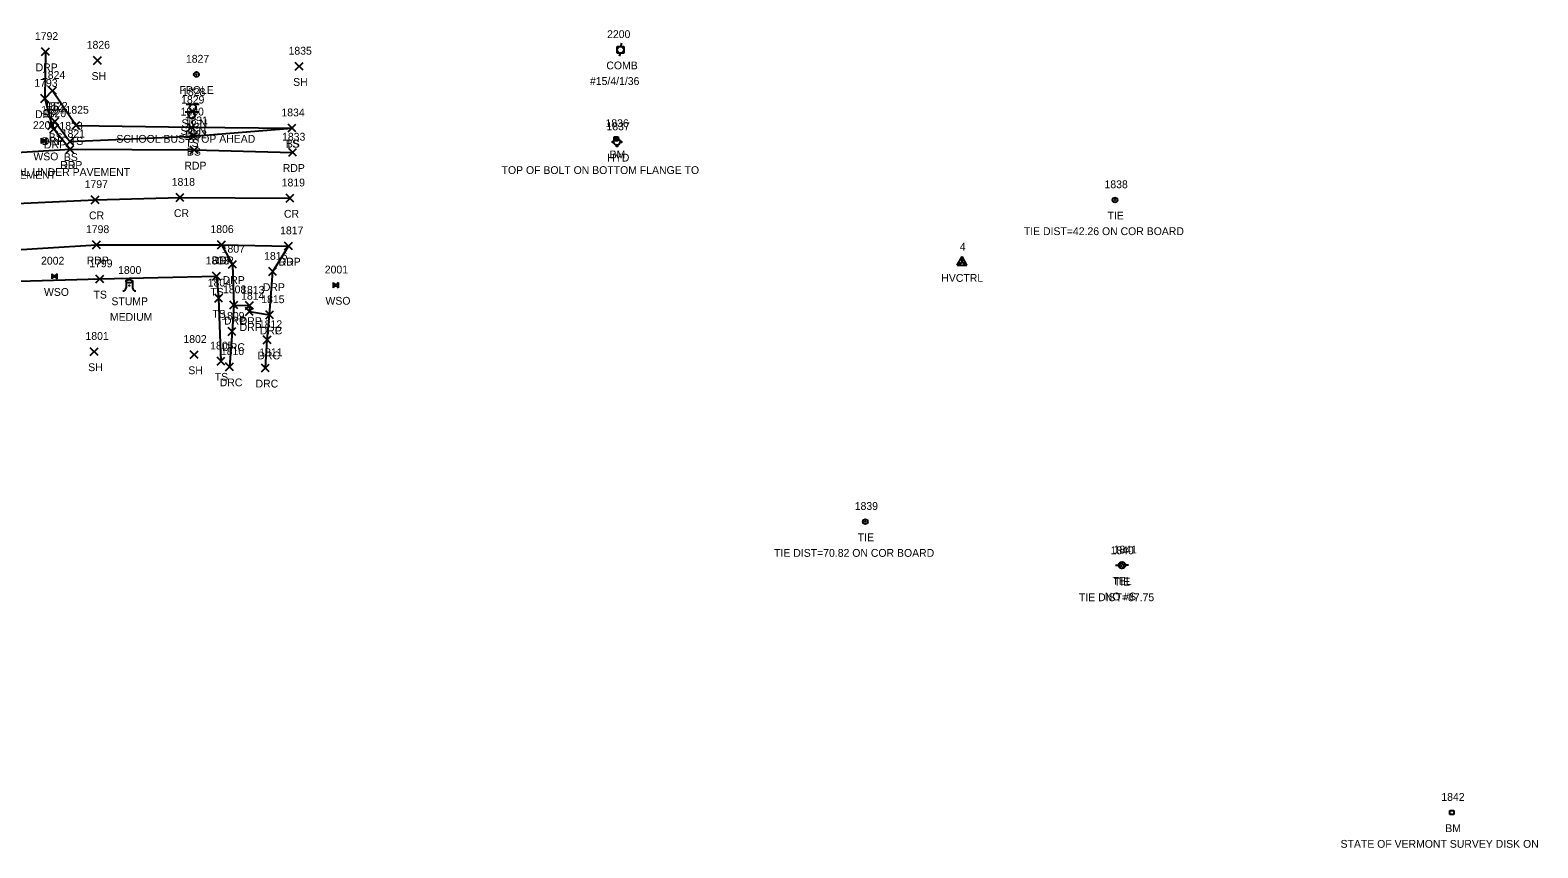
# Model space of a CAD drawing. Extents: x 1761340 to 1763889, y 696770 to 706023.
# Drawn here: x 1761969.7 to 1762355.3, y 700706.9 to 700916.1 of the extents above; entities that cross this region are included whole.
import ezdxf

# ---------------------------------------------------------------- set-up
doc = ezdxf.new("R2010")
doc.units = 0
for name, color, linetype in [('C_A', 7, 'Continuous'), ('C_C', 7, 'Continuous'), ('C_I', 7, 'Continuous'), ('CBP', 7, 'Continuous'), ('CPBM', 7, 'Continuous'), ('CPSM', 7, 'Continuous'), ('L_A', 7, 'Continuous'), ('L_C', 7, 'Continuous'), ('L_I', 7, 'Continuous'), ('L_TIC', 7, 'Continuous'), ('LELB', 7, 'Continuous'), ('LFP', 7, 'Continuous'), ('LTS', 7, 'Continuous'), ('P_A', 7, 'Continuous'), ('P_I', 7, 'Continuous'), ('P_TIC', 7, 'Continuous'), ('PET', 7, 'Continuous'), ('PRC', 7, 'Continuous'), ('R_A', 7, 'Continuous'), ('R_I', 7, 'Continuous'), ('R_TIC', 7, 'Continuous'), ('RDP', 7, 'Continuous'), ('S_A', 7, 'Continuous'), ('S_C', 7, 'Continuous'), ('S_I', 7, 'Continuous'), ('SSGN', 7, 'Continuous'), ('U_A', 7, 'Continuous'), ('U_C', 7, 'Continuous'), ('U_I', 7, 'Continuous'), ('UP', 7, 'Continuous'), ('UWFH', 7, 'Continuous'), ('UWV', 7, 'Continuous')]:
    doc.layers.add(name, color=color, linetype=linetype)

msp = doc.modelspace()

# ---------------------------------------------------------------- linework, layer by layer
at = {"layer": 'CBP'}
for centre, radius in [((1762247.16, 700872.67), 0.625), ((1762247.16, 700872.67), 0.0833), ((1762183.28, 700790.36), 0.625), ((1762183.28, 700790.36), 0.0833), ((1762248.79, 700779.01), 0.625), ((1762248.79, 700779.01), 0.0833)]:
    msp.add_circle(centre, radius, dxfattribs=at)
at = {"layer": 'CPBM'}
for p, q in [((1762119.07, 700887.8), (1762119.07, 700888.8)), ((1762119.07, 700888.8), (1762120.07, 700888.8)), ((1762120.07, 700887.8), (1762119.07, 700887.8)), ((1762119.58, 700888.3), (1762119.58, 700888.3)), ((1762119.58, 700888.3), (1762119.58, 700888.3)), ((1762120.07, 700888.8), (1762120.07, 700887.8)), ((1762332.81, 700715.42), (1762332.81, 700716.42)), ((1762332.81, 700716.42), (1762333.81, 700716.42)), ((1762333.81, 700716.42), (1762333.81, 700715.42)), ((1762333.81, 700715.42), (1762332.81, 700715.42)), ((1762333.31, 700715.92), (1762333.31, 700715.92)), ((1762333.31, 700715.92), (1762333.31, 700715.92))]:
    msp.add_line(p, q, dxfattribs=at)
at = {"layer": 'CPSM'}
for p, q in [((1762206.78, 700855.99), (1762208.03, 700858.16)), ((1762206.78, 700855.99), (1762208.03, 700856.72)), ((1762206.78, 700855.99), (1762209.28, 700855.99)), ((1762209.28, 700855.99), (1762208.03, 700858.16)), ((1762208.03, 700856.72), (1762208.03, 700858.16)), ((1762208.03, 700856.72), (1762208.03, 700856.72)), ((1762208.03, 700856.72), (1762209.28, 700855.99))]:
    msp.add_line(p, q, dxfattribs=at)
at = {"layer": 'L_TIC'}
for points in [[(1761985.89, 700907.36), (1761987.89, 700909.36)], [(1761987.89, 700907.36), (1761985.89, 700909.36)], [(1762037.46, 700905.84), (1762039.46, 700907.84)], [(1762039.46, 700905.84), (1762037.46, 700907.84)], [(1761974.38, 700899.63), (1761976.38, 700901.63)], [(1761976.38, 700899.63), (1761974.38, 700901.63)], [(1761974.98, 700891.72), (1761976.98, 700893.72)], [(1761976.98, 700891.72), (1761974.98, 700893.72)], [(1761980.41, 700890.74), (1761982.41, 700892.74)], [(1761982.41, 700890.74), (1761980.41, 700892.74)], [(1762009.93, 700890.26), (1762011.93, 700892.26)], [(1762011.93, 700890.26), (1762009.93, 700892.26)], [(1762010.32, 700888.01), (1762012.32, 700890.01)], [(1762012.32, 700888.01), (1762010.32, 700890.01)], [(1762035.63, 700890.05), (1762037.63, 700892.05)], [(1762037.63, 700890.05), (1762035.63, 700892.05)], [(1762035.63, 700890.05), (1762037.63, 700892.05)], [(1762037.63, 700890.05), (1762035.63, 700892.05)], [(1761978.85, 700886.63), (1761980.85, 700888.63)], [(1761980.85, 700886.63), (1761978.85, 700888.63)], [(1761986.48, 700851.44), (1761988.48, 700853.44)], [(1761988.48, 700851.44), (1761986.48, 700853.44)], [(1762016.34, 700852.16), (1762018.34, 700854.16)], [(1762018.34, 700852.16), (1762016.34, 700854.16)], [(1762016.87, 700846.52), (1762018.87, 700848.52)], [(1762018.87, 700846.52), (1762016.87, 700848.52)], [(1761985.03, 700832.87), (1761987.03, 700834.87)], [(1761987.03, 700832.87), (1761985.03, 700834.87)], [(1762010.64, 700832.08), (1762012.64, 700834.08)], [(1762012.64, 700832.08), (1762010.64, 700834.08)], [(1762017.48, 700830.41), (1762019.48, 700832.41)], [(1762019.48, 700830.41), (1762017.48, 700832.41)]]:
    msp.add_lwpolyline(points, dxfattribs=at)
at = {"layer": 'LELB'}
for points in [[(1761975.38, 700900.63), (1761981.41, 700891.74), (1762010.93, 700891.26), (1762036.63, 700891.05)], [(1761975.98, 700892.72), (1761979.85, 700887.63), (1762011.32, 700889.01), (1762036.63, 700891.05)], [(1761929.79, 700836.15), (1761931.22, 700849.05), (1761960.82, 700851.7), (1761987.48, 700852.44), (1762017.34, 700853.16), (1762017.87, 700847.52), (1762018.48, 700831.41)]]:
    msp.add_lwpolyline(points, dxfattribs=at)
at = {"layer": 'LFP'}
for radius in [0.625, 0.0833]:
    msp.add_circle((1762012.2, 700904.78), radius, dxfattribs=at)
at = {"layer": 'LTS'}
for p, q in [((1761994.19, 700851.88), (1761994.19, 700850.21)), ((1761995.86, 700851.71), (1761995.86, 700851.88)), ((1761995.86, 700851.88), (1761995.86, 700850.21)), ((1761995.03, 700850.74), (1761995.03, 700850.74)), ((1761995.03, 700850.74), (1761995.03, 700850.74)), ((1761995.03, 700850.71), (1761995.03, 700850.71))]:
    msp.add_line(p, q, dxfattribs=at)
msp.add_circle((1761995.03, 700850.74), 0.0833, dxfattribs=at)
for centre, start, end in [((1761993.36, 700850.21), 270, 360), ((1761996.69, 700850.21), 180, 270)]:
    msp.add_arc(centre, 0.833, start, end, dxfattribs=at)
msp.add_ellipse((1761995.03, 700851.88), major_axis=(-0.833, 0), ratio=0.5, dxfattribs=at)
at = {"layer": 'P_TIC'}
for points in [[(1761978.87, 700884.62), (1761980.87, 700886.62)], [(1761980.87, 700884.62), (1761978.87, 700886.62)], [(1762010.62, 700884.45), (1762012.62, 700886.45)], [(1762012.62, 700884.45), (1762010.62, 700886.45)], [(1762035.8, 700883.84), (1762037.8, 700885.84)], [(1762037.8, 700883.84), (1762035.8, 700885.84)], [(1761985.3, 700871.71), (1761987.3, 700873.71)], [(1761987.3, 700871.71), (1761985.3, 700873.71)], [(1762007.01, 700872.29), (1762009.01, 700874.29)], [(1762009.01, 700872.29), (1762007.01, 700874.29)], [(1762035.15, 700872.12), (1762037.15, 700874.12)], [(1762037.15, 700872.12), (1762035.15, 700874.12)], [(1761985.64, 700860.18), (1761987.64, 700862.18)], [(1761987.64, 700860.18), (1761985.64, 700862.18)], [(1762017.61, 700860.2), (1762019.61, 700862.2)], [(1762019.61, 700860.2), (1762017.61, 700862.2)], [(1762034.74, 700859.87), (1762036.74, 700861.87)], [(1762036.74, 700859.87), (1762034.74, 700861.87)]]:
    msp.add_lwpolyline(points, dxfattribs=at)
at = {"layer": 'PET'}
for points in [[(1761729.33, 700852.74), (1761740.9, 700853.18), (1761754.83, 700854.09), (1761780.55, 700856.28), (1761810.22, 700861.14), (1761821.19, 700866.01), (1761839.22, 700868.83), (1761861.11, 700872.05), (1761884.87, 700875.71), (1761913.75, 700879.27), (1761932.44, 700880.62), (1761962.06, 700884.59), (1761979.87, 700885.62), (1762011.62, 700885.45), (1762036.8, 700884.84)], [(1761729.33, 700852.74), (1761727.43, 700840.67), (1761725.47, 700828.38), (1761741.06, 700828.32), (1761766.65, 700830.86), (1761785.9, 700834.25), (1761810.86, 700839.79), (1761840.51, 700846.05), (1761863.89, 700848.79), (1761886.86, 700850.87), (1761909.09, 700853.95), (1761931.55, 700856.46), (1761961.83, 700859.61), (1761986.64, 700861.18), (1762018.61, 700861.2), (1762035.74, 700860.87)]]:
    msp.add_lwpolyline(points, dxfattribs=at)
at = {"layer": 'PRC'}
msp.add_lwpolyline([(1761727.43, 700840.67), (1761741.7, 700841.02), (1761763.59, 700842.8), (1761782.51, 700845.85), (1761809.01, 700850.75), (1761839.73, 700856.65), (1761862.6, 700860.14), (1761886.29, 700863.33), (1761916.3, 700867.26), (1761941.01, 700869.9), (1761962.56, 700871.62), (1761986.3, 700872.71), (1762008.01, 700873.29), (1762036.15, 700873.12)], dxfattribs=at)
at = {"layer": 'R_TIC'}
for points in [[(1761972.58, 700909.59), (1761974.58, 700911.59)], [(1761974.58, 700909.59), (1761972.58, 700911.59)], [(1761972.43, 700897.61), (1761974.43, 700899.61)], [(1761974.43, 700897.61), (1761972.43, 700899.61)], [(1761974.2, 700890.72), (1761976.2, 700892.72)], [(1761976.2, 700890.72), (1761974.2, 700892.72)], [(1761974.71, 700889.84), (1761976.71, 700891.84)], [(1761976.71, 700889.84), (1761974.71, 700891.84)], [(1761978.87, 700884.62), (1761980.87, 700886.62)], [(1761980.87, 700884.62), (1761978.87, 700886.62)], [(1762017.61, 700860.2), (1762019.61, 700862.2)], [(1762019.61, 700860.2), (1762017.61, 700862.2)], [(1762034.74, 700859.87), (1762036.74, 700861.87)], [(1762036.74, 700859.87), (1762034.74, 700861.87)], [(1762020.43, 700855.17), (1762022.43, 700857.17)], [(1762022.43, 700855.17), (1762020.43, 700857.17)], [(1762030.7, 700853.35), (1762032.7, 700855.35)], [(1762032.7, 700853.35), (1762030.7, 700855.35)], [(1762020.77, 700844.78), (1762022.77, 700846.78)], [(1762022.77, 700844.78), (1762020.77, 700846.78)], [(1762020.77, 700844.78), (1762022.77, 700846.78)], [(1762022.77, 700844.78), (1762020.77, 700846.78)], [(1762024.75, 700843.14), (1762026.75, 700845.14)], [(1762026.75, 700843.14), (1762024.75, 700845.14)], [(1762024.77, 700844.67), (1762026.77, 700846.67)], [(1762026.77, 700844.67), (1762024.77, 700846.67)], [(1762029.91, 700842.26), (1762031.91, 700844.26)], [(1762031.91, 700842.26), (1762029.91, 700844.26)], [(1762029.91, 700842.26), (1762031.91, 700844.26)], [(1762031.91, 700842.26), (1762029.91, 700844.26)], [(1762020.32, 700838.01), (1762022.32, 700840.01)], [(1762022.32, 700838.01), (1762020.32, 700840.01)], [(1762029.31, 700835.88), (1762031.31, 700837.88)], [(1762031.31, 700835.88), (1762029.31, 700837.88)], [(1762019.67, 700828.98), (1762021.67, 700830.98)], [(1762021.67, 700828.98), (1762019.67, 700830.98)], [(1762028.83, 700828.68), (1762030.83, 700830.68)], [(1762030.83, 700828.68), (1762028.83, 700830.68)]]:
    msp.add_lwpolyline(points, dxfattribs=at)
at = {"layer": 'RDP'}
for points in [[(1761973.58, 700910.59), (1761973.43, 700898.61), (1761975.2, 700891.72), (1761975.71, 700890.84), (1761979.87, 700885.62)], [(1762018.61, 700861.2), (1762021.43, 700856.17), (1762021.77, 700845.78), (1762025.77, 700845.67), (1762025.75, 700844.14), (1762030.91, 700843.26), (1762031.7, 700854.35), (1762035.74, 700860.87)], [(1762021.77, 700845.78), (1762021.32, 700839.01), (1762020.67, 700829.98)], [(1762029.83, 700829.68), (1762030.31, 700836.88), (1762030.91, 700843.26)]]:
    msp.add_lwpolyline(points, dxfattribs=at)
at = {"layer": 'SSGN'}
for p, q in [((1762009.36, 700895.18), (1762012.69, 700895.18)), ((1762009.59, 700897.16), (1762012.92, 700897.16)), ((1762011, 700894.35), (1762011, 700894.35)), ((1762011.24, 700896.32), (1762011.24, 700896.32))]:
    msp.add_line(p, q, dxfattribs=at)
for centre in [(1762011, 700894.35), (1762011.24, 700896.32)]:
    msp.add_circle(centre, 0.833, dxfattribs=at)
at = {"layer": 'UP'}
for p, q in [((1762119.83, 700910.25), (1762119.83, 700911.91)), ((1762119.83, 700911.91), (1762121.5, 700911.91)), ((1762121.5, 700910.25), (1762119.83, 700910.25)), ((1762120.42, 700909.41), (1762120.67, 700910.25)), ((1762120.92, 700912.75), (1762120.67, 700911.91)), ((1762120.67, 700911.08), (1762120.67, 700911.08)), ((1762121.5, 700911.91), (1762121.5, 700910.25)), ((1762247.28, 700779.2), (1762248.1, 700779.2)), ((1762248.94, 700779.21), (1762248.94, 700779.21)), ((1762250.6, 700779.21), (1762249.77, 700779.21)), ((1762249.77, 700779.21), (1762249.77, 700779.21)), ((1762250.6, 700779.21), (1762250.6, 700779.21))]:
    msp.add_line(p, q, dxfattribs=at)
for centre in [(1762120.67, 700911.08), (1762248.94, 700779.21)]:
    msp.add_circle(centre, 0.833, dxfattribs=at)
at = {"layer": 'UWFH'}
msp.add_line((1762119.77, 700887.5), (1762119.77, 700887.5), dxfattribs=at)
for centre, radius in [((1762118.77, 700887.5), 0.167), ((1762119.77, 700887.5), 0.833), ((1762119.77, 700886.5), 0.167), ((1762120.77, 700887.5), 0.167)]:
    msp.add_circle(centre, radius, dxfattribs=at)
at = {"layer": 'UWV'}
for p, q in [((1761972.5, 700888.46), (1761973.05, 700887.91)), ((1761973.05, 700887.68), (1761972.5, 700887.13)), ((1761973.83, 700888.46), (1761973.28, 700887.91)), ((1761973.28, 700887.68), (1761973.83, 700887.13)), ((1761975.21, 700853.79), (1761975.76, 700853.24)), ((1761975.76, 700853), (1761975.21, 700852.46)), ((1761976.54, 700853.79), (1761976, 700853.24)), ((1761976, 700853), (1761976.54, 700852.46)), ((1762047.21, 700851.53), (1762047.76, 700850.98)), ((1762048.54, 700851.53), (1762048, 700850.98)), ((1762047.76, 700850.74), (1762047.21, 700850.19)), ((1762048, 700850.74), (1762048.54, 700850.19))]:
    msp.add_line(p, q, dxfattribs=at)
for points in [[(1761972.5, 700888.46), (1761972.5, 700887.13)], [(1761973.83, 700887.13), (1761973.83, 700888.46)], [(1761975.21, 700853.79), (1761975.21, 700852.46)], [(1761976.54, 700852.46), (1761976.54, 700853.79)], [(1762047.21, 700851.53), (1762047.21, 700850.19)], [(1762048.54, 700850.19), (1762048.54, 700851.53)]]:
    msp.add_lwpolyline(points, dxfattribs=at)
for points in [[(1761973.4, 700887.8), (1761973.16, 700888.03), (1761972.93, 700887.8), (1761973.16, 700887.56)], [(1761976.11, 700853.12), (1761975.88, 700853.36), (1761975.64, 700853.12), (1761975.88, 700852.89)], [(1762048.11, 700850.86), (1762047.88, 700851.1), (1762047.64, 700850.86), (1762047.88, 700850.63)]]:
    msp.add_lwpolyline(points, close=True, dxfattribs=at)

# ---------------------------------------------------------------- texts
at = {"layer": 'C_A'}
for s, p in [('BM', (1762117.89, 700883.3)), ('TIE', (1762245.24, 700867.67)), ('HVCTRL', (1762202.72, 700851.72)), ('TIE', (1762181.36, 700785.36)), ('TIE', (1762246.87, 700774.01)), ('BM', (1762331.63, 700710.92))]:
    msp.add_text(s, height=2, dxfattribs=at).set_placement(p)
at = {"layer": 'C_C'}
for s, p in [('TOP OF BOLT ON BOTTOM FLANGE TO', (1762090.25, 700879.3)), ('TIE DIST=42.26 ON COR BOARD', (1762223.83, 700863.67)), ('TIE DIST=70.82 ON COR BOARD', (1762159.96, 700781.36)), ('TIE DIST=87.75', (1762237.92, 700770.01)), ('STATE OF VERMONT SURVEY DISK ON', (1762304.85, 700706.92))]:
    msp.add_text(s, height=2, dxfattribs=at).set_placement(p)
at = {"layer": 'C_I'}
for s, p in [('1836', (1762116.83, 700891.3)), ('1838', (1762244.47, 700875.67)), ('4', (1762207.46, 700859.72)), ('1839', (1762180.58, 700793.36)), ('1840', (1762246.01, 700782.01)), ('1842', (1762330.62, 700718.92))]:
    msp.add_text(s, height=2, dxfattribs=at).set_placement(p)
at = {"layer": 'L_A'}
for s, p in [('SH', (1761985.38, 700903.36)), ('FPOLE', (1762007.87, 700899.78)), ('SH', (1762036.94, 700901.84)), ('TS', (1761973.79, 700895.63)), ('BS', (1761974.42, 700887.72)), ('TS', (1761979.82, 700886.74)), ('TS', (1762009.34, 700886.26)), ('BS', (1762009.76, 700884.01)), ('TS', (1762035.04, 700886.05)), ('BS', (1762035.07, 700886.05)), ('BS', (1761978.29, 700882.63)), ('TS', (1761985.89, 700847.44)), ('STUMP', (1761990.45, 700845.74)), ('TS', (1762015.75, 700848.16)), ('TS', (1762016.28, 700842.52)), ('SH', (1761984.52, 700828.87)), ('SH', (1762010.13, 700828.08)), ('TS', (1762016.89, 700826.41))]:
    msp.add_text(s, height=2, dxfattribs=at).set_placement(p)
at = {"layer": 'L_C'}
msp.add_text('MEDIUM', height=2, dxfattribs=at).set_placement((1761990.08, 700841.74))
at = {"layer": 'L_I'}
for s, p in [('1826', (1761984.14, 700911.36)), ('1827', (1762009.51, 700907.78)), ('1835', (1762035.76, 700909.84)), ('1824', (1761972.69, 700903.63)), ('1822', (1761973.29, 700895.72)), ('1825', (1761978.72, 700894.74)), ('1830', (1762008.15, 700894.26)), ('1831', (1762009.2, 700892.01)), ('1834', (1762033.94, 700894.05)), ('1834', (1762033.94, 700894.05)), ('1823', (1761977.16, 700890.63)), ('1799', (1761984.78, 700855.44)), ('1800', (1761992.16, 700853.74)), ('1803', (1762014.57, 700856.16)), ('1804', (1762015.1, 700850.52)), ('1801', (1761983.82, 700836.87)), ('1802', (1762008.87, 700836.08)), ('1805', (1762015.71, 700834.41))]:
    msp.add_text(s, height=2, dxfattribs=at).set_placement(p)
at = {"layer": 'P_A'}
for s, p in [('RDP', (1761977.36, 700880.62)), ('RDP', (1762009.11, 700880.45)), ('RDP', (1762034.28, 700879.84)), ('CR', (1761984.73, 700867.71)), ('CR', (1762006.44, 700868.29)), ('CR', (1762034.58, 700868.12)), ('RDP', (1761984.13, 700856.18)), ('RDP', (1762016.1, 700856.2)), ('RDP', (1762033.22, 700855.87))]:
    msp.add_text(s, height=2, dxfattribs=at).set_placement(p)
at = {"layer": 'P_I'}
for s, p in [('1821', (1761977.75, 700888.62)), ('1832', (1762008.93, 700888.45)), ('1833', (1762034.1, 700887.84)), ('1818', (1762005.88, 700876.29)), ('1797', (1761983.61, 700875.71)), ('1819', (1762034.01, 700876.12)), ('1798', (1761983.95, 700864.18)), ('1806', (1762015.78, 700864.2)), ('1817', (1762033.61, 700863.87))]:
    msp.add_text(s, height=2, dxfattribs=at).set_placement(p)
at = {"layer": 'R_A'}
for s, p in [('DRP', (1761971.07, 700905.59)), ('DRP', (1761970.92, 700893.61)), ('DRP', (1761972.69, 700886.72)), ('DRP', (1761973.2, 700885.84)), ('DRP', (1761977.36, 700880.62)), ('DRP', (1762016.1, 700856.2)), ('DRP', (1762033.22, 700855.87)), ('DRP', (1762018.92, 700851.17)), ('DRP', (1762029.19, 700849.35)), ('DRC', (1762019.26, 700840.78)), ('DRP', (1762019.26, 700840.78)), ('DRP', (1762023.24, 700839.14)), ('DRP', (1762023.26, 700840.67)), ('DRC', (1762028.39, 700838.26)), ('DRP', (1762028.39, 700838.26)), ('DRC', (1762018.81, 700834.01)), ('DRC', (1762027.8, 700831.88)), ('DRC', (1762018.16, 700824.98)), ('DRC', (1762027.32, 700824.68))]:
    msp.add_text(s, height=2, dxfattribs=at).set_placement(p)
at = {"layer": 'R_I'}
for s, p in [('1792', (1761970.89, 700913.59)), ('1793', (1761970.74, 700901.61)), ('1794', (1761972.51, 700894.72)), ('1820', (1761972.93, 700893.84)), ('1821', (1761977.75, 700888.62)), ('1806', (1762015.78, 700864.2)), ('1817', (1762033.61, 700863.87)), ('1807', (1762018.66, 700859.17)), ('1816', (1762029.52, 700857.35)), ('1808', (1762019, 700848.78)), ('1808', (1762019, 700848.78)), ('1814', (1762023.63, 700847.14)), ('1813', (1762023.65, 700848.67)), ('1815', (1762028.78, 700846.26)), ('1815', (1762028.78, 700846.26)), ('1809', (1762018.54, 700842.01)), ('1812', (1762028.18, 700839.88)), ('1810', (1762018.46, 700832.98)), ('1811', (1762028.27, 700832.68))]:
    msp.add_text(s, height=2, dxfattribs=at).set_placement(p)
at = {"layer": 'S_A'}
for p in [(1762008.14, 700889.33), (1762008.38, 700891.3)]:
    msp.add_text('SIGN', height=2, dxfattribs=at).set_placement(p)
at = {"layer": 'S_C'}
msp.add_text('SCHOOL BUS STOP AHEAD', height=2, dxfattribs=at).set_placement((1761991.73, 700887.3))
at = {"layer": 'S_I'}
for s, p in [('1829', (1762008.28, 700897.33)), ('1828', (1762008.53, 700899.3))]:
    msp.add_text(s, height=2, dxfattribs=at).set_placement(p)
at = {"layer": 'U_A'}
for s, p in [('COMB', (1762117.05, 700906.08)), ('WSO', (1761970.5, 700882.8)), ('HYD', (1762117.29, 700882.5)), ('WSO', (1761973.21, 700848.12)), ('WSO', (1762045.21, 700845.86)), ('TEL', (1762246.5, 700774.21))]:
    msp.add_text(s, height=2, dxfattribs=at).set_placement(p)
at = {"layer": 'U_C'}
for s, p in [('#15/4/1/36', (1762112.86, 700902.08)), ('STRONG SIGNAL UNDER PAVEMENT', (1761928.58, 700878.07)), ('STRONG SIGNAL UNDER PAVEMENT', (1761947.55, 700878.8)), ('NO #S', (1762244.53, 700770.21))]:
    msp.add_text(s, height=2, dxfattribs=at).set_placement(p)
at = {"layer": 'U_I'}
for s, p in [('2200', (1762117.24, 700914.08)), ('2201', (1761970.39, 700890.8)), ('1837', (1762117.08, 700890.5)), ('2002', (1761972.46, 700856.12)), ('2001', (1762045.03, 700853.86)), ('1841', (1762246.81, 700782.21))]:
    msp.add_text(s, height=2, dxfattribs=at).set_placement(p)

doc.saveas('drawing.dxf')
